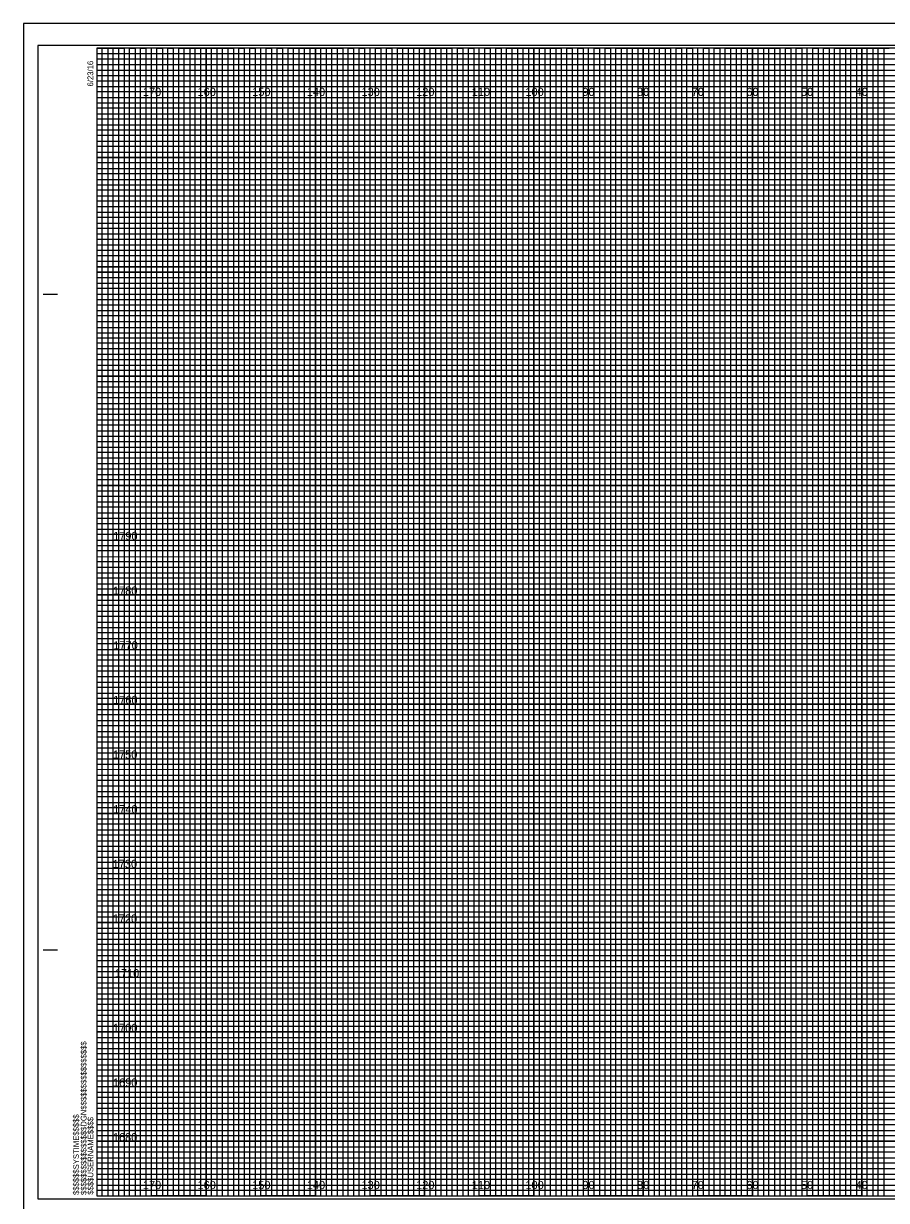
# Model space of a CAD drawing. Extents: x 1443 to 2205, y -29 to 5484.
# Drawn here: x 1867.8 to 2025.7, y 414.7 to 630.1 of the extents above; entities that cross this region are included whole.
import ezdxf

# ---------------------------------------------------------------- set-up
doc = ezdxf.new("R2010")
doc.units = 0
for name, color, linetype in [('Pattern 3', 7, 'Continuous'), ('Prop Retaining Wall', 7, 'Continuous'), ('Prop XS DDE Earthwork Shape', 7, 'Continuous'), ('Prop XS DDE Slope Text', 7, 'Continuous'), ('Prop XS DDE Text', 7, 'Continuous'), ('Prop XS Earthwork Shape', 7, 'Continuous'), ('Prop XS Retaining Wall', 7, 'Continuous'), ('Prop XS Station Labels', 7, 'Continuous'), ('Prop XS Temporary Shoring', 7, 'Continuous'), ('Raster_Level_0', 7, 'Continuous'), ('Scratch_Level_3', 7, 'Continuous')]:
    doc.layers.add(name, color=color, linetype=linetype)

msp = doc.modelspace()

# ---------------------------------------------------------------- linework, layer by layer
at = {"layer": 'Pattern 3'}
for p, q in [((2204.52, 630.05), (1867.82, 630.05)), ((1867.82, 630.05), (1867.82, 411.05))]:
    msp.add_line(p, q, dxfattribs=at)
at = {"layer": 'Prop Retaining Wall'}
for p, q in [((1881.22, 624.55), (2141.22, 624.55)), ((2141.22, 623.53), (1881.22, 623.53)), ((1881.22, 623.53), (1881.22, 622.55)), ((1881.22, 622.55), (2141.22, 622.55)), ((2141.22, 621.44), (1881.22, 621.44)), ((1881.22, 621.44), (1881.22, 619.55)), ((1881.22, 619.55), (2201.22, 619.55))]:
    msp.add_line(p, q, dxfattribs=at)
for points in [[(1881.22, 618.55), (2151.22, 618.55), (2201.22, 618.55), (2201.22, 617.55), (1881.22, 617.55)], [(1881.22, 616.55), (2201.22, 616.55), (2201.22, 614.55), (1881.22, 614.55)], [(1881.22, 613.55), (2201.22, 613.55), (2201.22, 612.55), (1881.22, 612.53)], [(1881.22, 611.55), (2201.22, 611.55), (2201.22, 609.55), (1881.22, 609.55)], [(1881.22, 608.55), (2201.22, 608.55), (2201.22, 607.55), (1881.22, 607.55)], [(1881.22, 606.55), (2201.22, 606.55), (2201.22, 604.55), (1881.22, 604.55)], [(1881.22, 603.55), (2201.22, 603.55), (2201.22, 602.55), (1881.22, 602.55)], [(1881.22, 601.55), (2201.22, 601.55), (2201.22, 599.55), (1881.22, 599.55)], [(1881.22, 598.55), (2201.22, 598.55), (2201.22, 597.55), (1881.22, 597.55)], [(1881.22, 596.55), (2201.22, 596.55), (2201.22, 594.55), (1881.22, 594.55)], [(1881.22, 593.55), (2201.22, 593.55), (2201.22, 592.55), (1881.22, 592.55)], [(1881.22, 591.55), (2201.22, 591.55), (2201.22, 589.5), (2201.22, 588.55), (2201.22, 587.55), (1881.22, 587.55)], [(1881.22, 589.55), (2201.22, 589.55), (2201.22, 588.55), (1881.22, 588.55)], [(1881.22, 586.55), (2201.22, 586.55), (2201.22, 584.55), (1881.22, 584.58)], [(1881.22, 584.58), (2201.22, 584.55), (2201.22, 583.55), (1881.22, 583.55)], [(1881.22, 582.55), (2201.22, 582.55), (2201.22, 581.55), (1881.22, 581.55)], [(1881.22, 579.55), (2201.22, 579.55), (2201.22, 578.55), (1881.22, 578.55)], [(1881.22, 577.55), (2201.22, 577.55), (2201.22, 576.55), (1881.22, 576.55)], [(1881.15, 574.44), (2201.22, 574.44), (2201.22, 573.43), (1881.15, 573.43)], [(1881.22, 572.55), (2201.22, 572.55), (2201.22, 571.55), (1881.22, 571.55)], [(1881.22, 569.55), (2201.22, 569.55), (2201.22, 568.55), (1881.22, 568.55)], [(1881.22, 567.55), (2201.22, 567.55), (2201.22, 566.55), (1881.22, 566.55)], [(1881.22, 564.55), (2201.22, 564.55), (2201.22, 563.55), (1881.22, 563.55)], [(1881.22, 562.55), (2201.22, 562.55), (2201.22, 561.55), (1881.22, 561.55)], [(1881.22, 559.55), (2201.22, 559.55), (2201.22, 558.55), (1881.22, 558.55)], [(1881.22, 557.55), (2201.22, 557.55), (2201.22, 556.55), (1881.22, 556.55)], [(1881.22, 554.55), (2201.22, 554.55), (2201.21, 553.53), (1881.22, 553.55)], [(1881.22, 552.55), (2201.22, 552.55), (2201.22, 551.55), (1881.22, 551.55)], [(1881.22, 549.55), (2201.22, 549.55), (2201.22, 548.55), (1881.22, 548.55)], [(1881.22, 547.55), (2201.22, 547.55), (2201.22, 546.55), (1881.22, 546.55)], [(1881.22, 544.55), (2201.22, 544.55), (2201.22, 543.55), (1881.22, 543.55)], [(1881.22, 542.55), (2201.22, 542.55), (2201.22, 541.55), (1881.22, 541.55)], [(1881.22, 539.55), (2201.22, 539.55), (2201.22, 538.55), (1881.22, 538.55)], [(1881.22, 537.55), (2201.22, 537.55), (2201.22, 536.55), (1881.22, 536.55)], [(1881.22, 534.55), (2201.22, 534.55), (2201.22, 533.55), (1881.22, 533.55)], [(1881.22, 532.54), (2201.29, 532.46), (2201.22, 531.55), (1881.22, 531.55)], [(1881.22, 529.55), (2201.22, 529.55), (2201.22, 528.55), (1881.22, 528.55)], [(1881.22, 527.55), (2201.22, 527.55), (2201.22, 526.55), (1881.22, 526.55)], [(1881.22, 524.55), (2201.22, 524.55), (2201.22, 523.55), (1881.22, 523.55)], [(1881.22, 522.55), (2201.22, 522.55), (2201.22, 521.55), (1881.22, 521.55)], [(1881.22, 519.55), (2201.22, 519.55), (2201.22, 518.55), (1881.22, 518.55)], [(1881.22, 517.55), (2201.22, 517.55), (2201.22, 516.55), (1881.22, 516.55)], [(1881.22, 514.55), (2201.22, 514.55), (2201.22, 513.55), (1881.22, 513.55)], [(1881.22, 512.55), (2201.22, 512.55), (2201.22, 511.55), (1881.22, 511.55)], [(1881.22, 509.55), (2201.22, 509.55), (2201.22, 508.55), (1881.22, 508.55)], [(1881.22, 507.55), (2201.22, 507.55), (2201.22, 506.55), (1881.22, 506.55)], [(1881.22, 504.55), (2201.22, 504.55), (2201.22, 503.55), (1881.22, 503.55)], [(1881.22, 502.55), (2201.22, 502.55), (2201.22, 501.55), (1881.22, 501.55)], [(1881.22, 499.55), (2201.22, 499.55), (2201.22, 498.55), (1881.22, 498.55)], [(1881.22, 497.55), (2201.22, 497.55), (2201.22, 496.55), (1881.22, 496.55)], [(1881.22, 494.55), (2201.22, 494.55), (2201.21, 493.53), (1881.22, 493.55)], [(1881.22, 492.55), (2201.22, 492.55), (2201.22, 491.55), (1881.22, 491.55)], [(1881.22, 489.55), (2201.22, 489.55), (2201.22, 488.55), (1881.22, 488.55)], [(1881.22, 487.55), (2201.22, 487.55), (2201.22, 486.55), (1881.22, 486.55)], [(1881.22, 484.55), (2201.22, 484.55), (2201.22, 483.55), (1881.22, 483.55)], [(1881.22, 482.55), (2201.22, 482.55), (2201.22, 481.55), (1881.22, 481.55)], [(1881.22, 479.55), (2201.22, 479.55), (2201.22, 478.55), (1881.22, 478.55)], [(1881.22, 477.55), (2201.22, 477.55), (2201.22, 476.55), (1881.22, 476.55)], [(1881.22, 474.55), (2201.22, 474.55), (2201.22, 473.55), (1881.22, 473.55)], [(1881.22, 472.54), (2201.29, 472.46), (2201.22, 471.55), (1881.22, 471.55)], [(1881.22, 469.55), (2201.22, 469.55), (2201.22, 468.55), (1881.22, 468.55)], [(1881.22, 467.55), (2201.22, 467.55), (2201.22, 466.55), (1881.22, 466.55)], [(1881.22, 464.55), (2201.22, 464.55), (2201.22, 463.55), (1881.22, 463.55)], [(1881.22, 462.55), (2201.22, 462.55), (2201.22, 461.55), (1881.22, 461.55)], [(1881.22, 459.55), (2201.22, 459.55), (2201.22, 458.55), (1881.22, 458.55)], [(1881.22, 457.55), (2201.22, 457.55), (2201.22, 456.55), (1881.22, 456.55)], [(1881.22, 454.55), (2201.22, 454.55), (2201.22, 453.55), (1881.22, 453.55)], [(1881.22, 452.55), (2201.22, 452.55), (2201.22, 451.55), (1881.22, 451.55)], [(1881.22, 449.55), (2201.22, 449.55), (2201.22, 448.55), (1881.22, 448.55)], [(1881.22, 447.55), (2201.22, 447.55), (2201.22, 446.55), (1881.22, 446.55)], [(1881.22, 444.55), (2201.22, 444.55), (2201.22, 443.55), (1881.22, 443.55)], [(1881.22, 442.55), (2201.22, 442.55), (2201.22, 441.55), (1881.22, 441.55)], [(1881.22, 439.55), (2201.22, 439.55), (2201.22, 438.55), (1881.22, 438.55)], [(1881.22, 437.55), (2201.22, 437.55), (2201.22, 436.55), (1881.22, 436.55)], [(1881.22, 434.55), (2201.22, 434.55), (2201.22, 433.55), (1881.22, 433.55)], [(1881.22, 432.55), (2201.22, 432.55), (2201.22, 431.55), (1881.22, 431.55)], [(1881.22, 429.55), (2201.22, 429.55), (2201.22, 428.55), (1881.22, 428.55)], [(1881.22, 427.55), (2201.22, 427.55), (2201.22, 426.55), (1881.22, 426.55)], [(1881.22, 424.55), (2201.22, 424.55), (2201.22, 423.55), (1881.22, 423.55)], [(1881.22, 422.55), (2201.22, 422.55), (2201.22, 421.55), (1881.22, 421.55)], [(1881.22, 419.55), (2201.22, 419.55), (2201.22, 418.55), (1881.22, 418.55)], [(1881.22, 417.55), (2201.22, 417.55), (2201.22, 416.55), (1881.22, 416.55)]]:
    msp.add_lwpolyline(points, dxfattribs=at)
at = {"layer": 'Prop XS DDE Earthwork Shape'}
msp.add_lwpolyline([(1870.42, 415.05), (2203.62, 415.05), (2203.62, 626.05), (1870.42, 626.05)], close=True, dxfattribs=at)
at = {"layer": 'Prop XS DDE Slope Text'}
for points in [[(1881.22, 415.55), (1882.22, 415.55), (1882.22, 625.55), (1883.22, 625.55), (1883.22, 415.55)], [(1883.22, 415.55), (1884.22, 415.55), (1884.22, 625.55), (1885.22, 625.55), (1885.22, 415.55)], [(1886.22, 415.55), (1887.22, 415.55), (1887.22, 625.55), (1888.22, 625.55), (1888.22, 415.55)], [(1888.22, 415.55), (1889.22, 415.55), (1889.22, 625.55), (1890.22, 625.55), (1890.22, 415.55)], [(1891.22, 415.55), (1892.22, 415.55), (1892.22, 625.55), (1893.22, 625.55), (1893.22, 415.55)], [(1893.22, 415.55), (1894.22, 415.55), (1894.22, 625.55), (1895.22, 625.55), (1895.22, 415.55)], [(1896.22, 415.55), (1897.22, 415.55), (1897.22, 625.55), (1898.22, 625.55), (1898.22, 415.55)], [(1898.22, 415.55), (1899.22, 415.55), (1899.22, 625.55), (1900.22, 625.55), (1900.22, 415.55)], [(1901.22, 415.55), (1902.22, 415.55), (1902.22, 625.55), (1903.22, 625.55), (1903.22, 415.55)], [(1903.22, 415.55), (1904.22, 415.55), (1904.22, 625.55), (1905.22, 625.55), (1905.22, 415.55)], [(1906.22, 415.55), (1907.22, 415.55), (1907.22, 625.55), (1908.22, 625.55), (1908.22, 415.55)], [(1908.22, 415.55), (1909.22, 415.55), (1909.22, 625.55), (1910.22, 625.55), (1910.22, 415.55)], [(1911.22, 415.55), (1912.22, 415.55), (1912.22, 625.55), (1913.22, 625.55), (1913.22, 415.55)], [(1913.22, 415.55), (1914.22, 415.55), (1914.22, 625.55), (1915.22, 625.55), (1915.22, 415.55)], [(1916.22, 415.55), (1917.22, 415.55), (1917.22, 625.55), (1918.22, 625.55), (1918.22, 415.55)], [(1918.22, 415.55), (1919.22, 415.55), (1919.22, 625.55), (1920.22, 625.55), (1920.22, 415.55)], [(1921.22, 415.55), (1922.22, 415.55), (1922.22, 625.55), (1923.22, 625.55), (1923.22, 415.55)], [(1923.22, 415.55), (1924.22, 415.55), (1924.22, 625.55), (1925.22, 625.55), (1925.22, 415.55)], [(1926.22, 415.55), (1927.22, 415.55), (1927.22, 625.55), (1928.22, 625.55), (1928.22, 415.55)], [(1928.22, 415.55), (1929.22, 415.55), (1929.22, 625.55), (1930.22, 625.55), (1930.22, 415.55)], [(1931.22, 415.55), (1932.22, 415.55), (1932.22, 625.55), (1933.22, 625.55), (1933.22, 415.55)], [(1933.22, 415.55), (1934.22, 415.55), (1934.22, 625.55), (1935.22, 625.55), (1935.22, 415.55)], [(1936.22, 415.55), (1937.22, 415.55), (1937.22, 625.55), (1938.22, 625.55), (1938.22, 415.55)], [(1938.22, 415.55), (1939.22, 415.55), (1939.22, 625.55), (1940.22, 625.55), (1940.22, 415.55)], [(1941.22, 415.55), (1942.22, 415.55), (1942.22, 625.55), (1943.22, 625.55), (1943.22, 415.55)], [(1943.22, 415.55), (1944.22, 415.55), (1944.22, 625.55), (1945.22, 625.55), (1945.22, 415.55)], [(1946.22, 415.55), (1947.22, 415.55), (1947.22, 625.55), (1948.22, 625.55), (1948.22, 415.55)], [(1948.22, 415.55), (1949.22, 415.55), (1949.22, 625.55), (1950.22, 625.55), (1950.22, 415.55)], [(1951.22, 415.55), (1952.22, 415.55), (1952.22, 625.55), (1953.22, 625.55), (1953.22, 415.55)], [(1953.22, 415.55), (1954.22, 415.55), (1954.22, 625.55), (1955.22, 625.55), (1955.22, 415.55)], [(1956.22, 415.55), (1957.22, 415.55), (1957.22, 625.55), (1958.22, 625.55), (1958.22, 415.55)], [(1958.22, 415.55), (1959.22, 415.55), (1959.22, 625.55), (1960.22, 625.55), (1960.22, 415.55)], [(1961.22, 415.55), (1962.22, 415.55), (1962.22, 625.55), (1963.22, 625.55), (1963.22, 415.55)], [(1963.22, 415.55), (1964.22, 415.55), (1964.22, 625.55), (1965.22, 625.55), (1965.22, 415.55)], [(1966.22, 415.55), (1967.22, 415.55), (1967.22, 625.55), (1968.22, 625.55), (1968.22, 415.55)], [(1968.22, 415.55), (1969.22, 415.55), (1969.22, 625.55), (1970.22, 625.55), (1970.22, 415.55)], [(1971.22, 415.55), (1972.22, 415.55), (1972.22, 625.55), (1973.22, 625.55), (1973.22, 415.55)], [(1973.22, 415.55), (1974.22, 415.55), (1974.22, 625.55), (1975.22, 625.55), (1975.22, 415.55)], [(1976.22, 415.55), (1977.22, 415.55), (1977.22, 625.55), (1978.22, 625.55), (1978.22, 415.55)], [(1978.22, 415.55), (1979.22, 415.55), (1979.22, 625.55), (1980.22, 625.55), (1980.22, 415.55)], [(1981.22, 415.55), (1982.22, 415.55), (1982.22, 625.55), (1983.22, 625.55), (1983.22, 415.55)], [(1983.22, 415.55), (1984.22, 415.55), (1984.22, 625.55), (1985.22, 625.55), (1985.22, 415.55)], [(1986.22, 415.55), (1987.22, 415.55), (1987.22, 625.55), (1988.22, 625.55), (1988.22, 415.55)], [(1988.22, 415.55), (1989.22, 415.55), (1989.22, 625.55), (1990.22, 625.55), (1990.22, 415.55)], [(1991.22, 415.55), (1992.22, 415.55), (1992.22, 625.55), (1993.22, 625.55), (1993.22, 415.55)], [(1993.22, 415.55), (1994.22, 415.55), (1994.22, 625.55), (1995.22, 625.55), (1995.22, 415.55)], [(1996.22, 415.55), (1997.22, 415.55), (1997.22, 625.55), (1998.22, 625.55), (1998.22, 415.55)], [(1998.22, 415.55), (1999.22, 415.55), (1999.22, 625.55), (2000.22, 625.55), (2000.22, 415.55)], [(2001.22, 415.55), (2002.22, 415.55), (2002.22, 625.55), (2003.22, 625.55), (2003.22, 415.55)], [(2003.22, 415.55), (2004.22, 415.55), (2004.22, 625.55), (2005.22, 625.55), (2005.22, 415.55)], [(2006.22, 415.55), (2007.22, 415.55), (2007.22, 625.55), (2008.22, 625.55), (2008.22, 415.55)], [(2008.22, 415.55), (2009.22, 415.55), (2009.22, 625.55), (2010.22, 625.55), (2010.22, 415.55)], [(2011.22, 415.55), (2012.22, 415.55), (2012.22, 625.55), (2013.22, 625.55), (2013.22, 415.55)], [(2013.22, 415.55), (2014.22, 415.55), (2014.22, 625.55), (2015.22, 625.55), (2015.22, 415.55)], [(2016.22, 415.55), (2017.22, 415.55), (2017.22, 625.55), (2018.22, 625.55), (2018.22, 415.55)], [(2018.22, 415.55), (2019.22, 415.55), (2019.22, 625.55), (2020.22, 625.55), (2020.22, 415.55)], [(2021.22, 415.55), (2022.22, 415.55), (2022.22, 625.55), (2023.22, 625.55), (2023.22, 415.55)], [(2023.22, 415.55), (2024.22, 415.55), (2024.22, 625.55), (2025.22, 625.55), (2025.22, 415.55)]]:
    msp.add_lwpolyline(points, dxfattribs=at)
at = {"layer": 'Prop XS DDE Text'}
msp.add_lwpolyline([(1867.82, 411.05), (2204.52, 411.05), (2204.52, 630.05), (1867.82, 630.05)], close=True, dxfattribs=at)
at = {"layer": 'Prop XS Earthwork Shape'}
for p, q in [((1891.22, 625.55), (1881.22, 625.55)), ((1891.22, 415.55), (1891.22, 625.55)), ((1911.22, 625.55), (1901.22, 625.55)), ((1901.22, 625.55), (1901.22, 415.55)), ((1911.22, 415.55), (1911.22, 625.55)), ((1931.22, 625.55), (1921.22, 625.55)), ((1921.22, 625.55), (1921.22, 415.55)), ((1931.22, 415.55), (1931.22, 625.55)), ((1951.22, 625.55), (1941.22, 625.55)), ((1941.22, 625.55), (1941.22, 415.55)), ((1951.22, 415.55), (1951.22, 625.55)), ((1971.22, 625.55), (1961.22, 625.55)), ((1961.22, 625.55), (1961.22, 415.55)), ((1971.22, 415.55), (1971.22, 625.55)), ((1991.22, 625.55), (1981.22, 625.55)), ((1981.22, 625.55), (1981.22, 415.55)), ((1991.22, 415.55), (1991.22, 625.55)), ((2011.22, 625.55), (2001.22, 625.55)), ((2001.22, 625.55), (2001.22, 415.55)), ((2011.22, 415.55), (2011.22, 625.55)), ((2031.22, 625.55), (2021.22, 625.55)), ((2021.22, 625.55), (2021.22, 415.55)), ((1901.22, 415.55), (1891.22, 415.55)), ((1921.22, 415.55), (1911.22, 415.55)), ((1941.22, 415.55), (1931.22, 415.55)), ((1961.22, 415.55), (1951.22, 415.55)), ((1981.22, 415.55), (1971.22, 415.55)), ((2001.22, 415.55), (1991.22, 415.55)), ((2021.22, 415.55), (2011.22, 415.55))]:
    msp.add_line(p, q, dxfattribs=at)
for points in [[(1881.22, 615.55), (2201.22, 615.55), (2201.22, 605.55), (1881.22, 605.55)], [(1881.22, 595.55), (2201.22, 595.55), (2201.22, 585.55), (1881.22, 585.55)], [(1881.22, 575.55), (2201.22, 575.55), (2201.22, 565.55), (1881.22, 565.55)], [(1881.22, 555.55), (2201.22, 555.55), (2201.22, 545.55), (1881.22, 545.55)], [(1881.22, 535.55), (2201.22, 535.55), (2201.22, 525.55), (1881.22, 525.55)], [(1881.22, 515.55), (2201.22, 515.55), (2201.22, 505.55), (1881.22, 505.55)], [(1881.22, 495.55), (2201.22, 495.55), (2201.22, 485.55), (1881.22, 485.55)], [(1881.22, 475.55), (2201.22, 475.55), (2201.22, 465.55), (1881.22, 465.55)], [(1881.22, 455.55), (2201.22, 455.55), (2201.22, 445.55), (1881.22, 445.55)], [(1881.22, 435.55), (2201.22, 435.55), (2201.22, 425.55), (1881.22, 425.55)]]:
    msp.add_lwpolyline(points, dxfattribs=at)
at = {"layer": 'Prop XS Retaining Wall'}
for p, q in [((1871.42, 580.55), (1873.92, 580.55)), ((1871.52, 580.55), (1874.02, 580.55)), ((1871.42, 460.55), (1873.92, 460.55)), ((1871.52, 460.55), (1874.02, 460.55)), ((1881.22, 415.55), (1881.22, 415.55)), ((1881.22, 415.55), (1881.22, 415.55)), ((1881.22, 415.55), (1881.22, 415.55)), ((1881.22, 415.55), (1881.22, 415.55)), ((1881.22, 415.55), (1881.22, 415.55)), ((1881.22, 415.55), (1881.22, 415.55)), ((1881.22, 415.55), (1881.22, 415.55))]:
    msp.add_line(p, q, dxfattribs=at)
msp.add_lwpolyline([(2201.22, 625.55), (1881.22, 625.55), (1881.22, 415.55), (2201.22, 415.55)], close=True, dxfattribs=at)
at = {"layer": 'Prop XS Station Labels'}
for points in [[(1881.22, 625.55), (1886.22, 625.55), (1886.22, 415.55), (1896.22, 415.55), (1896.22, 625.55), (1906.22, 625.55), (1906.22, 415.55), (1916.22, 415.55), (1916.22, 625.55), (1926.22, 625.55), (1926.22, 415.55), (1936.22, 415.55), (1936.22, 625.55), (1946.22, 625.55), (1946.22, 415.55), (1956.22, 415.55), (1956.22, 625.55), (1966.22, 625.55), (1966.22, 415.55), (1976.22, 415.55), (1976.22, 625.55), (1986.22, 625.55), (1986.22, 415.55), (1996.22, 415.55), (1996.22, 625.55), (2006.22, 625.55), (2006.22, 415.55), (2016.22, 415.55), (2016.22, 625.55), (2026.22, 625.55)], [(1881.22, 620.55), (2156.22, 620.55)], [(1881.22, 600.55), (2201.22, 600.55), (2201.22, 610.55), (1881.22, 610.55)], [(1881.22, 580.55), (2201.22, 580.55), (2201.22, 590.55), (1881.22, 590.55)], [(1881.22, 560.55), (2201.22, 560.55), (2201.22, 570.55), (1881.22, 570.55)], [(1881.22, 540.55), (2201.22, 540.55), (2201.22, 550.55), (1881.22, 550.55)], [(1881.22, 520.55), (2201.22, 520.55), (2201.22, 530.55), (1881.22, 530.55)], [(1881.22, 500.55), (2201.22, 500.55), (2201.22, 510.55), (1881.22, 510.55)], [(1881.22, 480.55), (2201.22, 480.55), (2201.22, 490.55), (1881.22, 490.55)], [(1881.22, 460.55), (2201.22, 460.55), (2201.22, 470.55), (1881.22, 470.55)], [(1881.22, 440.55), (2201.22, 440.55), (2201.22, 450.55), (1881.22, 450.55)], [(1881.22, 420.55), (2201.22, 420.55), (2201.22, 430.55), (1881.22, 430.55)]]:
    msp.add_lwpolyline(points, dxfattribs=at)
at = {"layer": 'Prop XS Temporary Shoring'}
for p, q in [((1891.22, 415.55), (1891.22, 625.55)), ((1901.22, 415.55), (1901.22, 625.55)), ((1911.22, 415.55), (1911.22, 625.55)), ((1921.22, 415.55), (1921.22, 625.55)), ((1931.22, 415.55), (1931.22, 625.55)), ((1941.22, 415.55), (1941.22, 625.55)), ((1951.22, 415.55), (1951.22, 625.55)), ((1961.22, 415.55), (1961.22, 625.55)), ((1971.22, 415.55), (1971.22, 625.55)), ((1981.22, 415.55), (1981.22, 625.55)), ((1991.22, 415.55), (1991.22, 625.55)), ((2001.22, 415.55), (2001.22, 625.55)), ((2011.22, 415.55), (2011.22, 625.55)), ((2021.22, 415.55), (2021.22, 625.55)), ((1881.22, 615.55), (2201.22, 615.55)), ((1881.22, 605.55), (2201.22, 605.55)), ((1881.22, 595.55), (2201.22, 595.55)), ((1881.22, 585.55), (2201.22, 585.55)), ((1881.22, 575.55), (2201.22, 575.55)), ((1881.22, 565.55), (2201.22, 565.55)), ((1881.22, 555.55), (2201.22, 555.55)), ((1881.22, 545.55), (2201.22, 545.55)), ((1881.22, 535.55), (2201.22, 535.55)), ((1881.22, 525.55), (2201.22, 525.55)), ((1881.22, 515.55), (2201.22, 515.55)), ((1881.22, 505.55), (2201.22, 505.55)), ((1881.22, 495.55), (2201.22, 495.55)), ((1881.22, 485.55), (2201.22, 485.55)), ((1881.22, 475.55), (2201.22, 475.55)), ((1881.22, 465.55), (2201.22, 465.55)), ((1881.22, 455.55), (2201.22, 455.55)), ((1881.22, 445.55), (2201.22, 445.55)), ((1881.22, 435.55), (2201.22, 435.55)), ((1881.22, 425.55), (2201.22, 425.55))]:
    msp.add_line(p, q, dxfattribs=at)

# ---------------------------------------------------------------- texts
at = {"layer": 'Prop XS Retaining Wall'}
for s, p in [('6/23/16', (1880.57, 618.55)), ('$$$$$$$$$$$$$$$$DGN$$$$$$$$$$$$$$$$', (1879.34, 415.73)), ('$$$$$$SYSTIME$$$$$', (1877.96, 415.73)), ('$$$$USERNAME$$$$', (1880.6, 415.78))]:
    msp.add_text(s, height=1.05, rotation=90, dxfattribs=at).set_placement(p)
at = {"layer": 'Raster_Level_0'}
for s, p in [('170', (1889.66, 616.8)), ('160', (1899.66, 616.8)), ('150', (1909.66, 616.8)), ('140', (1919.66, 616.8)), ('130', (1929.66, 616.8)), ('120', (1939.66, 616.8)), ('110', (1949.84, 616.8)), ('100', (1959.66, 616.8)), ('90', (1970.08, 616.8)), ('80', (1980.08, 616.8)), ('70', (1990.08, 616.8)), ('60', (2000.08, 616.8)), ('50', (2010.08, 616.8)), ('40', (2020.08, 616.8)), ('170', (1889.66, 416.8)), ('160', (1899.66, 416.8)), ('150', (1909.66, 416.8)), ('140', (1919.66, 416.8)), ('130', (1929.66, 416.8)), ('120', (1939.66, 416.8)), ('110', (1949.84, 416.8)), ('100', (1959.66, 416.8)), ('90', (1970.08, 416.8)), ('80', (1980.08, 416.8)), ('70', (1990.08, 416.8)), ('60', (2000.08, 416.8)), ('50', (2010.08, 416.8)), ('40', (2020.08, 416.8))]:
    msp.add_text(s, height=1.5, dxfattribs=at).set_placement(p)
at = {"layer": 'Scratch_Level_3'}
for s, p in [('1790', (1884.22, 535.55)), ('1780', (1884.2, 525.55)), ('1770', (1884.26, 515.55)), ('1760', (1884.22, 505.55)), ('1750', (1884.18, 495.55)), ('1740', (1884.22, 485.55)), ('1730', (1884.14, 475.55)), ('1720', (1884.15, 465.55)), ('1710', (1884.53, 455.55)), ('1700', (1884.2, 445.55)), ('1690', (1884.19, 435.55)), ('1680', (1884.17, 425.55))]:
    msp.add_text(s, height=1.5, dxfattribs=at).set_placement(p)

doc.saveas('drawing.dxf')
